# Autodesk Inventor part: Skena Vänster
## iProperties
Created: 2001-12
Part Number: Skena Vänster
Material: S235JRG2
Document SubType Name: Modeling
Designer: Tobben
Control State: 0
Master: False
Checked Out: False
Shininess: 64.0
Length Units: 11269
Angle Units: 11279
Time Units: 11290
Mass Units: 11283
Length Display Precision: 3
Angle Display Precision: 2
Density: 0.0
Volumn: 0.0
Area: 0.0
PropertySet Name: Model Information
Author: Tobben
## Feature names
1. Extrusion1
2. Hole1
3. Rectangular Pattern1
4. Hole2
5. Extrusion3
6. Extrusion4
